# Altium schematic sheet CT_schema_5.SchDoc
size 278 x 161 mm
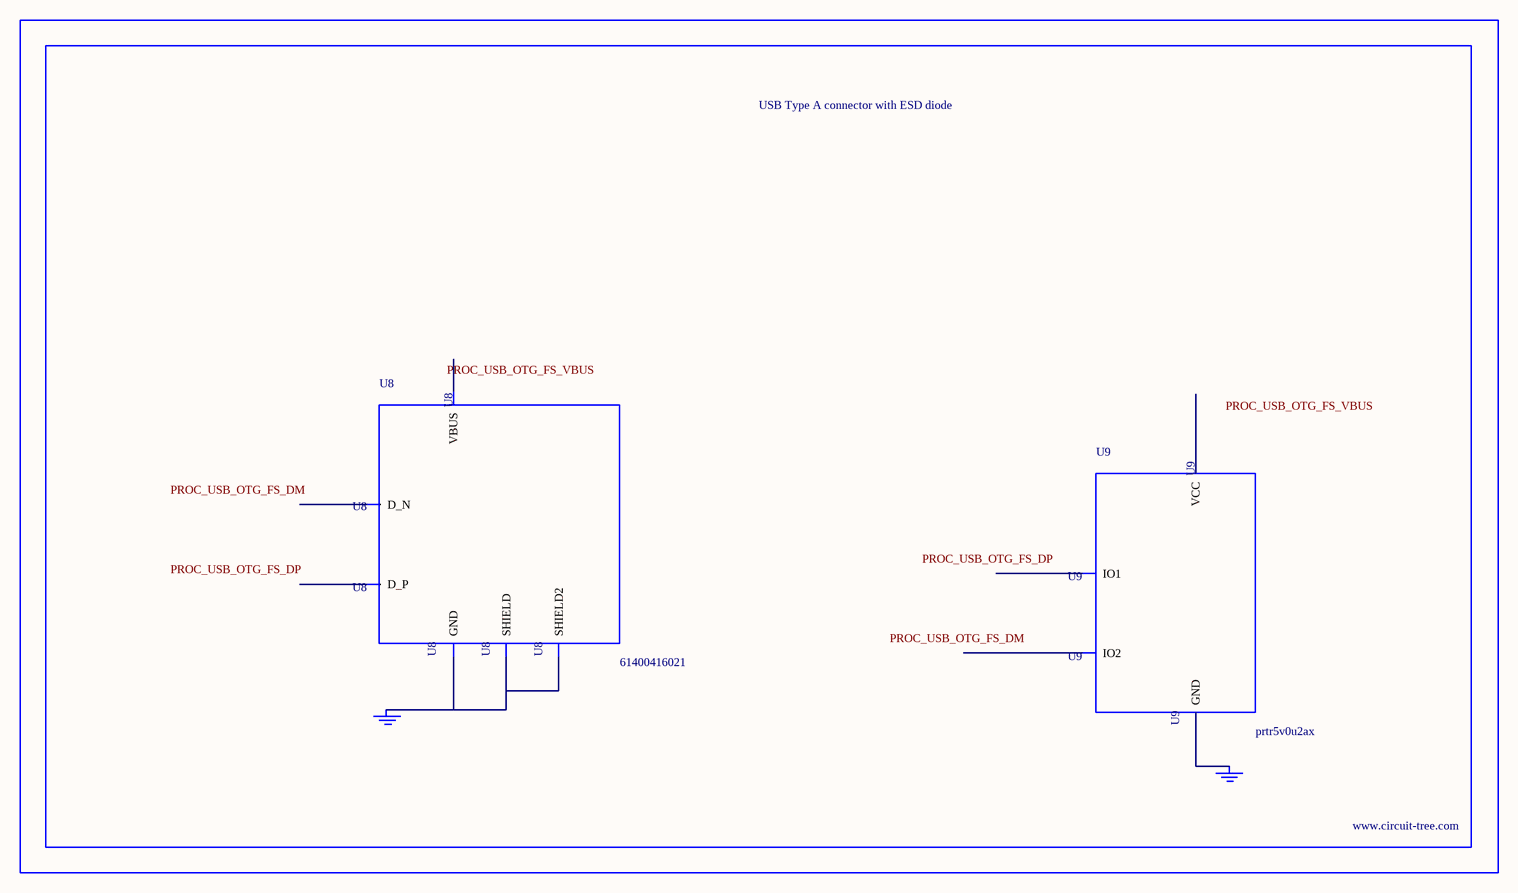
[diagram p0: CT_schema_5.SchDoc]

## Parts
BORDER4  (no value)
GND_INSTANCE_4_0  (no value)
GND_INSTANCE_4_1  (no value)
U8  61400416021  [USB-A-H]
U9  prtr5v0u2ax  [SOT143B]

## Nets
NetGND_INSTANCE_4_0_0: GND_INSTANCE_4_0.0(GND) U8.4(GND) U8.5(SHIELD) U8.6(SHIELD2)
NetGND_INSTANCE_4_1_0: GND_INSTANCE_4_1.0(GND) U9.1(GND)

Not connected (* = marked no-connect by the designer): U8 1(VBUS) 2(D_N) 3(D_P); U9 2(IO1) 3(IO2) 4(VCC)

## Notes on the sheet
- Labels drawn without touching a wire or pin: PROC_USB_OTG_FS_DM, PROC_USB_OTG_FS_DP, PROC_USB_OTG_FS_VBUS

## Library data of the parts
BORDER4 = BORDER_PAGE4
GND_INSTANCE_4_0 GND_INSTANCE_4_1 = GND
